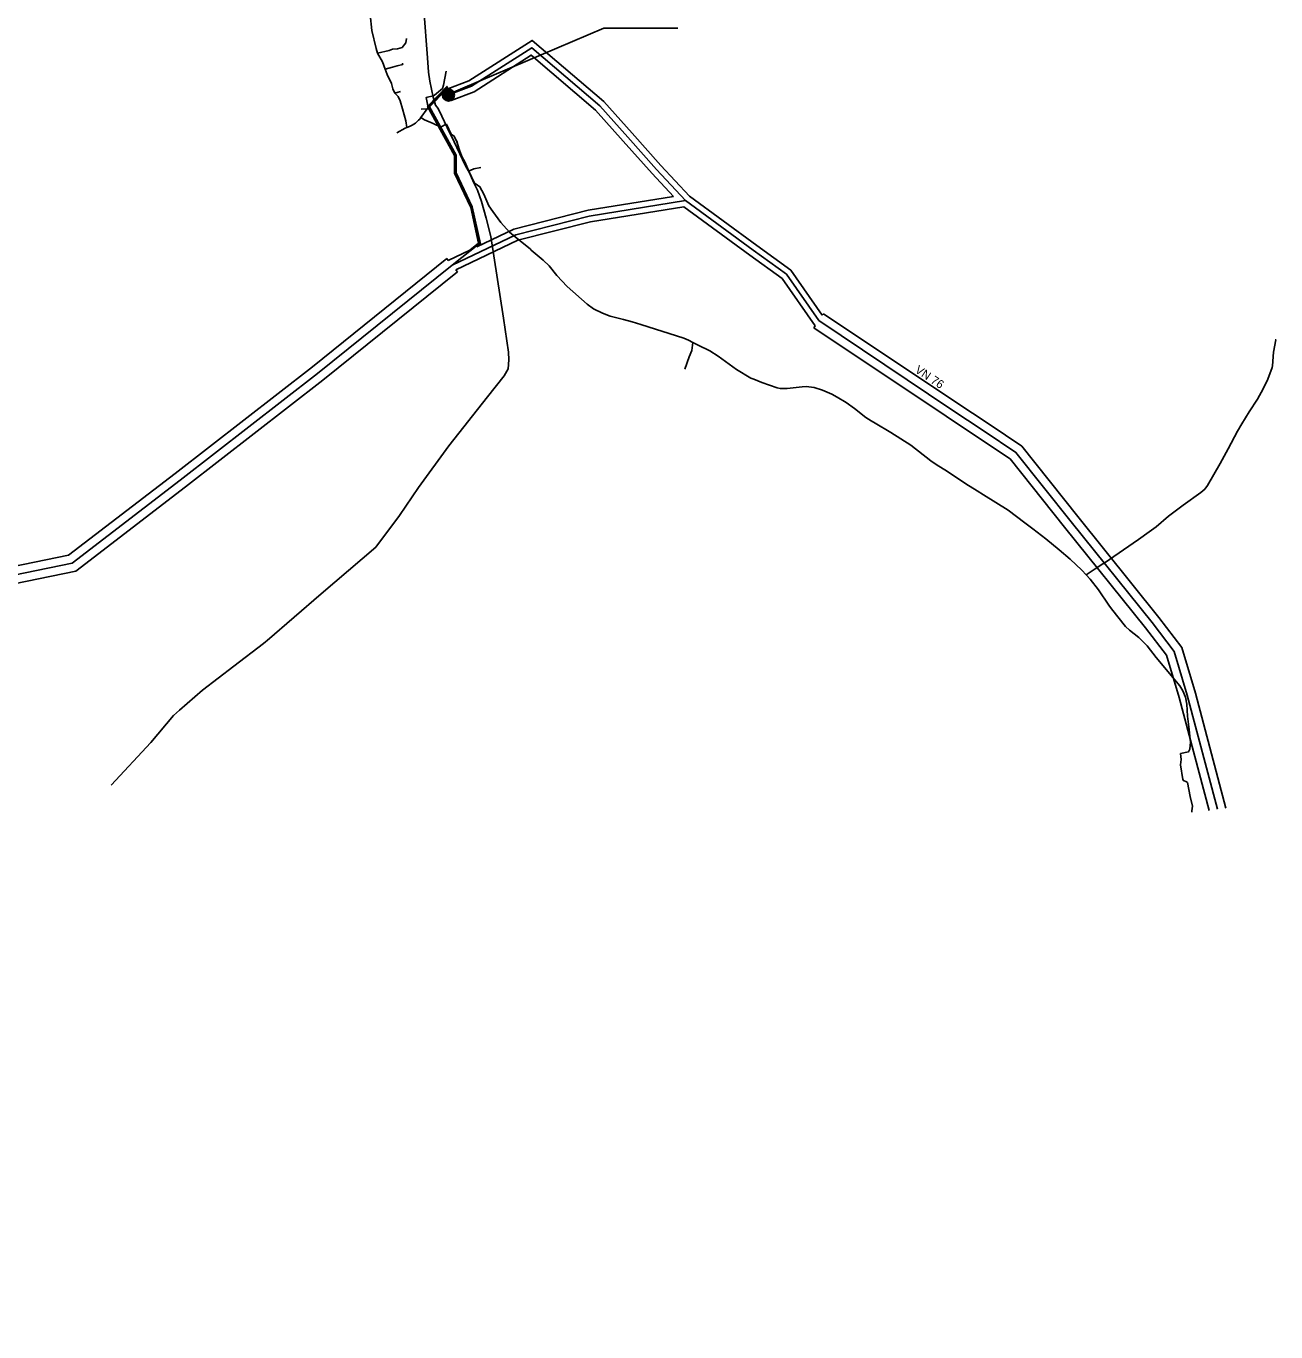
# Model space of a CAD drawing. Extents: x -546883 to -534032, y -1096714 to -1090569.
# Drawn here: x -540404 to -538929, y -1093938 to -1092397 of the extents above; entities that cross this region are included whole.
import ezdxf

# ---------------------------------------------------------------- set-up
doc = ezdxf.new("R2010")
doc.units = 0
for name, color, linetype in [('Vrstva 17', 7, 'Continuous'), ('Vrstva 18', 7, 'Continuous'), ('Vrstva 2', 7, 'Continuous'), ('Vrstva 23', 7, 'Continuous'), ('Vrstva 4', 7, 'Continuous')]:
    doc.layers.add(name, color=color, linetype=linetype)

msp = doc.modelspace()

# ---------------------------------------------------------------- linework, layer by layer
at = {"layer": 'Vrstva 17'}
for points in [[(-539934.3, -1092377.7), (-539930, -1092434.2), (-539928.9, -1092451.3), (-539927.4, -1092461.8), (-539923.4, -1092480.5), (-539920.7, -1092490.1), (-539917.4, -1092494.1), (-539913.1, -1092503.3), (-539903.5, -1092523.2), (-539901.8, -1092526.6), (-539885.6, -1092561.1), (-539880.1, -1092570.9), (-539879.2, -1092572.9), (-539875.1, -1092581.8), (-539870.8, -1092590.5), (-539866.1, -1092603.8), (-539860.6, -1092623.4), (-539855.2, -1092645.1), (-539840.2, -1092741.6), (-539834.2, -1092781.8), (-539834.1, -1092790.8), (-539834.9, -1092801.2), (-539839.6, -1092809.8), (-539859.2, -1092834.4), (-539904.6, -1092892.1), (-539940.6, -1092941.3), (-539962.9, -1092974.5), (-539991.1, -1093011.8), (-540055.3, -1093067.1), (-540119.3, -1093122.1), (-540121.1, -1093123.5), (-540123.7, -1093125.4), (-540158.5, -1093152.4), (-540195.7, -1093180.7), (-540222.7, -1093204.3), (-540229.8, -1093210.7), (-540256.5, -1093242.4), (-540303.2, -1093292.7)], [(-539997.8, -1092383.2), (-539995.6, -1092402.1), (-539990.7, -1092423.1), (-539988.9, -1092428.9)], [(-539988.9, -1092428.9), (-539975.3, -1092425.6), (-539971.2, -1092423.9), (-539965.3, -1092423.6), (-539960, -1092422), (-539955.4, -1092416.6), (-539954.7, -1092411.5)], [(-539988.9, -1092428.9), (-539982.9, -1092438.9), (-539980, -1092447.8)], [(-539980, -1092447.8), (-539971.4, -1092445.1), (-539965.9, -1092443.8), (-539959.2, -1092442.1), (-539959.4, -1092440.4)], [(-539980, -1092447.8), (-539977.7, -1092454.1), (-539972.3, -1092464.5), (-539970.9, -1092470.9), (-539968.4, -1092475.8)], [(-539930.5, -1092494.5), (-539929.1, -1092492.7), (-539931.5, -1092481), (-539923.3, -1092479.2), (-539921.6, -1092478.5), (-539912.2, -1092470.6), (-539911.2, -1092466.7), (-539908, -1092450.1)], [(-539968.4, -1092475.8), (-539964.5, -1092474.7), (-539961.7, -1092473.9)], [(-539968.4, -1092475.8), (-539964.6, -1092479.9), (-539962.3, -1092484.9), (-539959.5, -1092494.6), (-539955.6, -1092508.6), (-539954.4, -1092516.6)], [(-539954.4, -1092516.6), (-539951.1, -1092515.2), (-539948.1, -1092513.9), (-539944.3, -1092511.3), (-539941.5, -1092508.7)], [(-539941.5, -1092508.7), (-539940.7, -1092507.9)], [(-539940.7, -1092507.9), (-539939.1, -1092506.5), (-539937.7, -1092504.7)], [(-539937.7, -1092504.7), (-539930.5, -1092494.5)], [(-539937.7, -1092504.7), (-539933.4, -1092507.6), (-539923.2, -1092511.9), (-539914.4, -1092516), (-539913.2, -1092515.4), (-539908.6, -1092513), (-539907.6, -1092512.6), (-539902.1, -1092524.2), (-539898.4, -1092526.7), (-539895.4, -1092533.6), (-539894.5, -1092535.9), (-539892.1, -1092543.2), (-539890, -1092549.7), (-539888.9, -1092551.7), (-539886.1, -1092557), (-539881.1, -1092568.2), (-539875, -1092581.6), (-539873.7, -1092582.6), (-539868.1, -1092586.4), (-539863.4, -1092595.2), (-539857.7, -1092609.1), (-539852.7, -1092615.6), (-539843.3, -1092628.6), (-539833.2, -1092640), (-539824.3, -1092647.7), (-539808.8, -1092659.8), (-539807.5, -1092661.2), (-539793.3, -1092672.9), (-539786.5, -1092679.9), (-539777.2, -1092691.3), (-539765.2, -1092704.1), (-539741.4, -1092725.2), (-539734, -1092730.4), (-539723.4, -1092735.6), (-539714.2, -1092739.2), (-539698.6, -1092743.1), (-539688.4, -1092745.9), (-539678, -1092749.2), (-539627.3, -1092765.2), (-539621.8, -1092767.5), (-539616.8, -1092770.1), (-539610.6, -1092773.5), (-539596.8, -1092780), (-539587.1, -1092786.5), (-539565.1, -1092802.3), (-539548.2, -1092812.2), (-539544.8, -1092813.7), (-539535.3, -1092817.5), (-539517.4, -1092823.9), (-539513.7, -1092824.5), (-539505.3, -1092824.5), (-539487.9, -1092822.6), (-539483.2, -1092822.3), (-539473.8, -1092823.4), (-539463.6, -1092826.4), (-539452.7, -1092831.2), (-539446.4, -1092834.7), (-539435.8, -1092841.2), (-539426.1, -1092848.1), (-539412.8, -1092858.7), (-539406.3, -1092862.9), (-539401.7, -1092865.3), (-539383.3, -1092876.4), (-539359.6, -1092891.5), (-539335.8, -1092909.8), (-539328.3, -1092915.2), (-539317.4, -1092921.9), (-539294.6, -1092936.9), (-539281.4, -1092945.4), (-539273.6, -1092950), (-539244.7, -1092968.2), (-539224.8, -1092983.1), (-539215.6, -1092990.3), (-539200.4, -1093002.1), (-539184.5, -1093015), (-539171.4, -1093026.2), (-539157.8, -1093038.9), (-539152.7, -1093044.3), (-539147.7, -1093049.6), (-539138, -1093062.2), (-539126, -1093080.2), (-539122.7, -1093084.8), (-539106.3, -1093105.6), (-539101.6, -1093110), (-539090.6, -1093118.5), (-539080.5, -1093128.4), (-539070, -1093141.9), (-539042.2, -1093175.4), (-539038.6, -1093181.4), (-539035.5, -1093188.7), (-539033.6, -1093197), (-539033.1, -1093211.4), (-539031.3, -1093224.1), (-539029.5, -1093242.2), (-539030.4, -1093250.2), (-539031.8, -1093253.4), (-539041.2, -1093255.5), (-539040.3, -1093262.5), (-539041.3, -1093268.6), (-539038.4, -1093286.2), (-539037.8, -1093287.4), (-539034.3, -1093288.7), (-539033, -1093289.8), (-539029.7, -1093306.1), (-539027.1, -1093317.4), (-539027.8, -1093323.1), (-539027.8, -1093324.5)], [(-539930.5, -1092494.5), (-539937.3, -1092494.7)], [(-539954.4, -1092516.6), (-539956.5, -1092517.2), (-539966.3, -1092522.6)], [(-539914.4, -1092516), (-539914.7, -1092516.2)], [(-539895.4, -1092533.6), (-539894.2, -1092533.2)], [(-539888.9, -1092551.7), (-539888.3, -1092551.5)], [(-539881.1, -1092568.2), (-539879.6, -1092567.1), (-539875.4, -1092565.1), (-539867, -1092563.9)], [(-539626.1, -1092801.7), (-539621.2, -1092787.1), (-539618, -1092779.8), (-539616.8, -1092770.1)], [(-539152.7, -1093044.3), (-539142.1, -1093037.3), (-539132.9, -1093031.6), (-539131.3, -1093030.6), (-539090.9, -1093002.9), (-539078.4, -1092993.7), (-539070.1, -1092987.8), (-539055.4, -1092975.4), (-539038.2, -1092962.4), (-539017.1, -1092947.3), (-539012.6, -1092943.5), (-539009.4, -1092939.2), (-538994.6, -1092913.2), (-538985, -1092895.7), (-538973.9, -1092874.9), (-538968.8, -1092866.1), (-538960.3, -1092852.2), (-538950.4, -1092837.2), (-538943.7, -1092824.9), (-538938.3, -1092813.7), (-538933, -1092799.9), (-538932.5, -1092797.8), (-538931.4, -1092781.6), (-538928.7, -1092767.3), (-538929.6, -1092767.1)]]:
    msp.add_lwpolyline(points, dxfattribs=at)
at = {"layer": 'Vrstva 18'}
for p, q in [((-539902.2, -1092484.5), (-539908.1, -1092472)), ((-539907.3, -1092671.2), (-539905.5, -1092673.4)), ((-539896.5, -1092684.6), (-539894.7, -1092686.8)), ((-539464, -1092738), (-539462.8, -1092736.3)), ((-539474, -1092752.9), (-539472.3, -1092750.4))]:
    msp.add_line(p, q, dxfattribs=at)
for points in [[(-539906, -1092470.9), (-539881.1, -1092461.6), (-539806.4, -1092413.7), (-539721.8, -1092486), (-539688.4, -1092523.2), (-539654.6, -1092561.3), (-539620.9, -1092597.4), (-539541.4, -1092655.8), (-539501.2, -1092684.8), (-539464, -1092738)], [(-539639.6, -1092597.8), (-539664.9, -1092570.7), (-539698.9, -1092532.5), (-539731.6, -1092496), (-539807.6, -1092431.1), (-539874.8, -1092474.2), (-539902.2, -1092484.5)], [(-539879.9, -1092661.1), (-539869.7, -1092653.1), (-539879, -1092610.8), (-539898, -1092570.5), (-539898, -1092549.7), (-539929.9, -1092491.8), (-539907.1, -1092468), (-539906, -1092470.9)], [(-539908.1, -1092472), (-539927.5, -1092492.1), (-539896, -1092549.2), (-539896, -1092570), (-539877.1, -1092610.2), (-539867.4, -1092653.9), (-539871.7, -1092657.2)], [(-539871.7, -1092657.2), (-539828.2, -1092636.4), (-539740.5, -1092614.2), (-539639.6, -1092597.8)], [(-539627.4, -1092610), (-539737.7, -1092627.9), (-539823.4, -1092649.6), (-539896.5, -1092684.6)], [(-539472.3, -1092750.4), (-539511.3, -1092694.8), (-539549.7, -1092667.1), (-539627.4, -1092610)], [(-539905.5, -1092673.4), (-539879.9, -1092661.1)], [(-542258.8, -1093485.2), (-542110, -1093456.9), (-541311.2, -1093304.2), (-541205.3, -1093270.5), (-541047.6, -1093201.3), (-540943.3, -1093142.6), (-540715.2, -1093095.7), (-540353.7, -1093021.3), (-540227.9, -1092924.7), (-540065.8, -1092798.9), (-539907.3, -1092671.2)], [(-539894.7, -1092686.8), (-540053.4, -1092814.6), (-540215.6, -1092940.5), (-540345.2, -1093040), (-540711.2, -1093115.3), (-540936.2, -1093161.6), (-541038.6, -1093219.2), (-541198.2, -1093289.2), (-541306.3, -1093323.6), (-542106.2, -1093476.6), (-542264.5, -1093506.6), (-542408.5, -1093576.9), (-542515.2, -1093665.6), (-542690.4, -1093891.8), (-542773.7, -1093901.3), (-543058.2, -1093938.1)], [(-539462.8, -1092736.3), (-539306.6, -1092840.7), (-539267.2, -1092866.7), (-539228.6, -1092892.7), (-539162.4, -1092975.8), (-539066.9, -1093094.7), (-539039.7, -1093130.2), (-539023.7, -1093184), (-538987.6, -1093319.9)], [(-539007.6, -1093322.5), (-539043, -1093189.4), (-539057.9, -1093139.5), (-539082.6, -1093107), (-539178, -1092988.3), (-539242.3, -1092907.5), (-539278.3, -1092883.4), (-539317.7, -1092857.3), (-539474, -1092752.9)]]:
    msp.add_lwpolyline(points, dxfattribs=at)
at = {"layer": 'Vrstva 2'}
msp.add_lwpolyline([(-539905.2, -1092478.2), (-539905.3, -1092478), (-539904.5, -1092477.6), (-539904.7, -1092477.1), (-539907.4, -1092469.8), (-539928.7, -1092492), (-539897, -1092549.4), (-539897, -1092570.2), (-539878, -1092610.5), (-539868.5, -1092653.5), (-539901, -1092679)], dxfattribs=at)
at = {"layer": 'Vrstva 23'}
for points in [[(-538997.6, -1093321.2), (-539033.3, -1093186.7), (-539048.8, -1093134.9), (-539074.8, -1093100.8), (-539170.2, -1092982.1), (-539235.5, -1092900.1), (-539272.8, -1092875.1), (-539312.2, -1092849), (-539468.1, -1092744.2), (-539506.3, -1092689.8), (-539545.5, -1092661.4), (-539625.6, -1092602.6), (-539659.7, -1092566), (-539693.7, -1092527.8), (-539726.7, -1092491), (-539807, -1092422.4), (-539877.9, -1092467.9), (-539905.2, -1092478.1), (-539905.2, -1092478.2)], [(-539625.6, -1092602.6), (-539739.1, -1092621), (-539825.8, -1092643), (-539901, -1092679), (-540059.6, -1092806.8), (-540221.8, -1092932.6), (-540349.5, -1093030.7), (-540713.2, -1093105.5), (-540939.8, -1093152.1), (-541043.1, -1093210.2), (-541201.8, -1093279.9), (-541308.7, -1093313.9), (-542108.1, -1093466.7), (-542267.6, -1093497.1), (-542413.9, -1093568.4), (-542522.5, -1093658.6), (-542695.7, -1093882.3), (-542774.9, -1093891.3), (-543062.5, -1093928.5)]]:
    msp.add_lwpolyline(points, dxfattribs=at)
at = {"layer": 'Vrstva 4'}
msp.add_lwpolyline([(-539906.8, -1092477.8), (-539721.9, -1092399.4), (-539634.6, -1092399.4)], dxfattribs=at)
for radius in [7.03, 6.09, 5.16, 4.22, 3.28, 2.34, 1.41, 0.469]:
    msp.add_circle((-539905.2, -1092478.2), radius, dxfattribs=at)

# ---------------------------------------------------------------- texts
at = {"layer": 'Vrstva 23'}
msp.add_text('VN 76', height=10, rotation=326.2291, dxfattribs=at).set_placement((-539355.5, -1092804.8))

doc.saveas('drawing.dxf')
